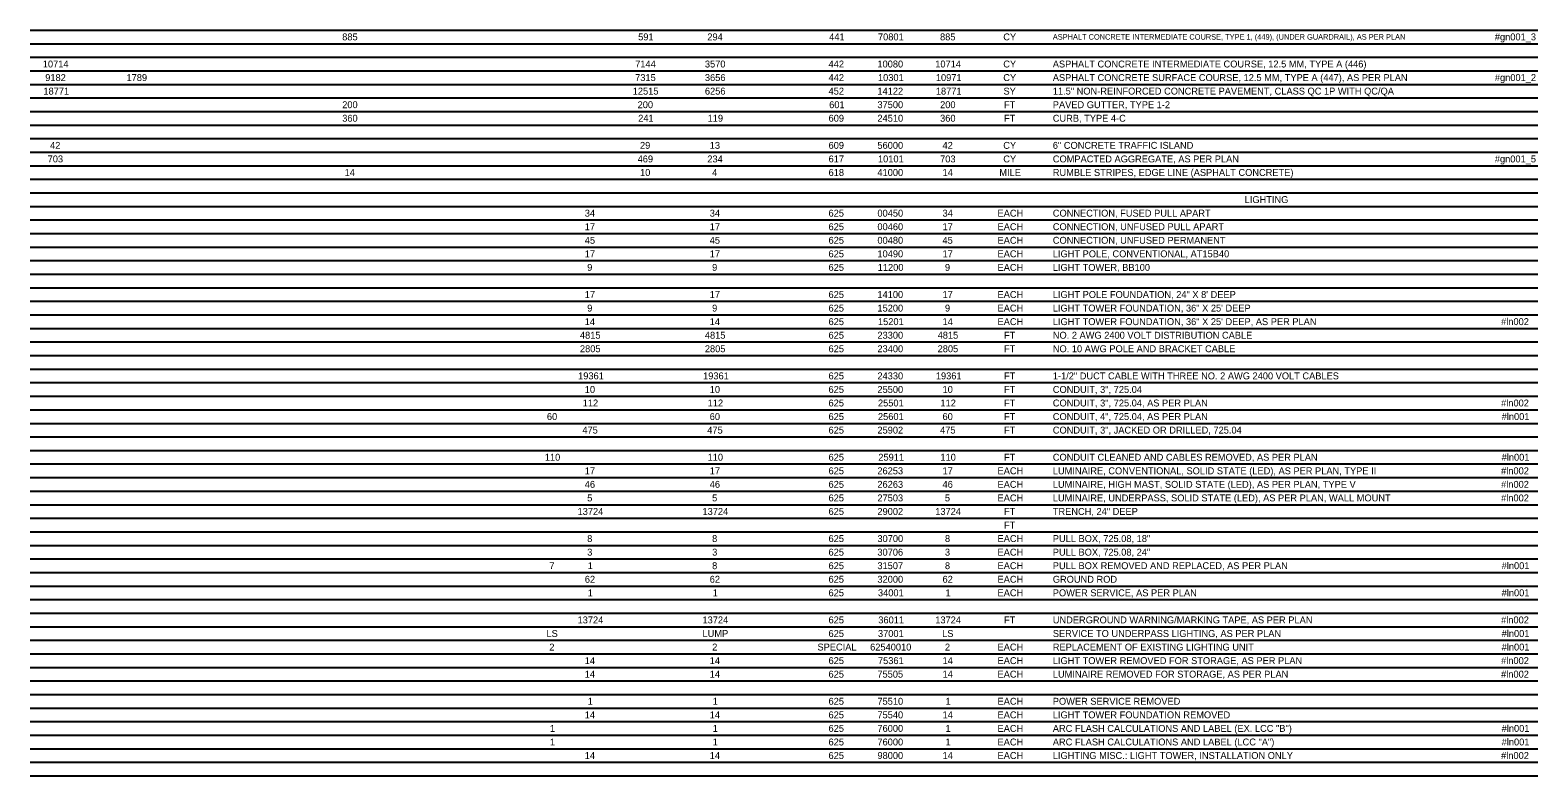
# Model space of a CAD drawing. Extents: x -542 to 295, y -281 to 32.
# Drawn here: x -366.31 to -335.81, y -89.91 to -74.81 of the extents above; entities that cross this region are included whole.
import ezdxf

# ---------------------------------------------------------------- set-up
doc = ezdxf.new("R2010")
doc.units = 0
doc.layers.add('SH_Data', color=7, linetype='Continuous')
doc.layers.add('SH_Text', color=7, linetype='Continuous')

msp = doc.modelspace()

# ---------------------------------------------------------------- linework, layer by layer
at = {"layer": 'SH_Data'}
for p, q in [((-366.307, -74.812), (-335.807, -74.812)), ((-366.307, -75.087), (-335.807, -75.087)), ((-366.307, -75.361), (-335.807, -75.361)), ((-366.307, -75.636), (-335.807, -75.636)), ((-366.307, -75.91), (-335.807, -75.91)), ((-366.307, -76.185), (-335.807, -76.185)), ((-366.307, -76.459), (-335.807, -76.459)), ((-366.307, -76.734), (-335.807, -76.734)), ((-366.307, -77.008), (-335.807, -77.008)), ((-366.307, -77.283), (-335.807, -77.283)), ((-366.307, -77.557), (-335.807, -77.557)), ((-366.307, -77.832), (-335.807, -77.832)), ((-366.307, -78.106), (-335.807, -78.106)), ((-366.307, -78.381), (-335.807, -78.381)), ((-366.307, -78.655), (-335.807, -78.655)), ((-366.307, -78.93), (-335.807, -78.93)), ((-366.307, -79.204), (-335.807, -79.204)), ((-366.307, -79.479), (-335.807, -79.479)), ((-366.307, -79.753), (-335.807, -79.753)), ((-366.307, -80.028), (-335.807, -80.028)), ((-366.307, -80.302), (-335.807, -80.302)), ((-366.307, -80.577), (-335.807, -80.577)), ((-366.307, -80.851), (-335.807, -80.851)), ((-366.307, -81.126), (-335.807, -81.126)), ((-366.307, -81.4), (-335.807, -81.4)), ((-366.307, -81.675), (-335.807, -81.675)), ((-366.307, -81.949), (-335.807, -81.949)), ((-366.307, -82.224), (-335.807, -82.224)), ((-366.307, -82.498), (-335.807, -82.498)), ((-366.307, -82.773), (-335.807, -82.773)), ((-366.307, -83.047), (-335.807, -83.047)), ((-366.307, -83.322), (-335.807, -83.322)), ((-366.307, -83.596), (-335.807, -83.596)), ((-366.307, -83.871), (-335.807, -83.871)), ((-366.307, -84.145), (-335.807, -84.145)), ((-366.307, -84.42), (-335.807, -84.42)), ((-366.307, -84.694), (-335.807, -84.694)), ((-366.307, -84.969), (-335.807, -84.969)), ((-366.307, -85.243), (-335.807, -85.243)), ((-366.307, -85.518), (-335.807, -85.518)), ((-366.307, -85.792), (-335.807, -85.792)), ((-366.307, -86.067), (-335.807, -86.067)), ((-366.307, -86.341), (-335.807, -86.341)), ((-366.307, -86.616), (-335.807, -86.616)), ((-366.307, -86.89), (-335.807, -86.89)), ((-366.307, -87.165), (-335.807, -87.165)), ((-366.307, -87.44), (-335.807, -87.44)), ((-366.307, -87.714), (-335.807, -87.714)), ((-366.307, -87.989), (-335.807, -87.989)), ((-366.307, -88.263), (-335.807, -88.263)), ((-366.307, -88.538), (-335.807, -88.538)), ((-366.307, -88.812), (-335.807, -88.812)), ((-366.307, -89.087), (-335.807, -89.087)), ((-366.307, -89.361), (-335.807, -89.361)), ((-366.307, -89.636), (-335.807, -89.636)), ((-366.307, -89.91), (-335.807, -89.91))]:
    msp.add_line(p, q, dxfattribs=at)

# ---------------------------------------------------------------- texts
at = {"layer": 'SH_Text'}
for s, height, p in [('885', 0.14, (-359.994, -75.019)), ('591', 0.14, (-354.007, -75.019)), ('294', 0.14, (-352.608, -75.019)), ('441', 0.14, (-350.143, -75.019)), ('70801', 0.14, (-349.156, -75.019)), ('885', 0.14, (-347.9, -75.019)), ('CY', 0.14, (-346.621, -75.019)), ('ASPHALT CONCRETE INTERMEDIATE COURSE, TYPE 1, (449), (UNDER GUARDRAIL), AS PER PLAN', 0.112, (-345.619, -75.005)), ('#gn001_3', 0.14, (-336.677, -75.019)), ('10714', 0.14, (-366.051, -75.568)), ('7144', 0.14, (-354.067, -75.568)), ('3570', 0.14, (-352.657, -75.568)), ('442', 0.14, (-350.155, -75.568)), ('10080', 0.14, (-349.167, -75.568)), ('10714', 0.14, (-347.997, -75.568)), ('CY', 0.14, (-346.621, -75.568)), ('ASPHALT CONCRETE INTERMEDIATE COURSE, 12.5 MM, TYPE A (446)', 0.14, (-345.619, -75.568)), ('9182', 0.14, (-366.002, -75.843)), ('1789', 0.14, (-364.358, -75.843)), ('7315', 0.14, (-354.068, -75.843)), ('3656', 0.14, (-352.657, -75.843)), ('442', 0.14, (-350.155, -75.843)), ('10301', 0.14, (-349.156, -75.843)), ('10971', 0.14, (-347.985, -75.843)), ('CY', 0.14, (-346.621, -75.843)), ('ASPHALT CONCRETE SURFACE COURSE, 12.5 MM, TYPE A (447), AS PER PLAN', 0.14, (-345.619, -75.843)), ('#gn001_2', 0.14, (-336.676, -75.843)), ('18771', 0.14, (-366.039, -76.117)), ('200', 0.14, (-359.994, -76.392)), ('12515', 0.14, (-354.117, -76.117)), ('200', 0.14, (-354.018, -76.392)), ('6256', 0.14, (-352.657, -76.117)), ('452', 0.14, (-350.155, -76.117)), ('601', 0.14, (-350.143, -76.392)), ('37500', 0.14, (-349.167, -76.392)), ('14122', 0.14, (-349.167, -76.117)), ('18771', 0.14, (-347.985, -76.117)), ('200', 0.14, (-347.899, -76.392)), ('SY', 0.14, (-346.617, -76.117)), ('11.5" NON-REINFORCED CONCRETE PAVEMENT, CLASS QC 1P WITH QC/QA', 0.14, (-345.619, -76.117)), ('PAVED GUTTER, TYPE 1-2', 0.14, (-345.619, -76.392)), ('360', 0.14, (-359.994, -76.666)), ('241', 0.14, (-354.007, -76.666)), ('119', 0.14, (-352.602, -76.666)), ('609', 0.14, (-350.155, -76.666)), ('24510', 0.14, (-349.167, -76.666)), ('360', 0.14, (-347.899, -76.666)), ('FT', 0.14, (-346.606, -76.392)), ('FT', 0.14, (-346.606, -76.666)), ('CURB, TYPE 4-C', 0.14, (-345.619, -76.666)), ('42', 0.14, (-365.904, -77.215)), ('29', 0.14, (-353.97, -77.215)), ('13', 0.14, (-352.559, -77.215)), ('609', 0.14, (-350.155, -77.215)), ('56000', 0.14, (-349.167, -77.215)), ('42', 0.14, (-347.85, -77.215)), ('CY', 0.14, (-346.621, -77.215)), ('6" CONCRETE TRAFFIC ISLAND', 0.14, (-345.619, -77.215)), ('703', 0.14, (-365.953, -77.49)), ('469', 0.14, (-354.018, -77.49)), ('234', 0.14, (-352.608, -77.49)), ('617', 0.14, (-350.155, -77.49)), ('10101', 0.14, (-349.156, -77.49)), ('703', 0.14, (-347.899, -77.49)), ('CY', 0.14, (-346.621, -77.49)), ('COMPACTED AGGREGATE, AS PER PLAN', 0.14, (-345.619, -77.49)), ('#gn001_5', 0.14, (-336.677, -77.49)), ('14', 0.14, (-359.945, -77.764)), ('10', 0.14, (-353.969, -77.764)), ('4', 0.14, (-352.51, -77.764)), ('618', 0.14, (-350.155, -77.764)), ('41000', 0.14, (-349.167, -77.764)), ('14', 0.14, (-347.85, -77.764)), ('MILE', 0.14, (-346.701, -77.764)), ('RUMBLE STRIPES, EDGE LINE (ASPHALT CONCRETE)', 0.14, (-345.619, -77.764)), ('LIGHTING', 0.14, (-341.738, -78.313)), ('34', 0.14, (-355.087, -78.588)), ('34', 0.14, (-352.559, -78.588)), ('625', 0.14, (-350.156, -78.588)), ('00450', 0.14, (-349.167, -78.588)), ('34', 0.14, (-347.85, -78.588)), ('EACH', 0.14, (-346.737, -78.588)), ('CONNECTION, FUSED PULL APART', 0.14, (-345.619, -78.588)), ('17', 0.14, (-355.087, -78.862)), ('17', 0.14, (-352.559, -78.862)), ('625', 0.14, (-350.156, -78.862)), ('625', 0.14, (-350.156, -79.137)), ('00460', 0.14, (-349.167, -78.862)), ('00480', 0.14, (-349.167, -79.137)), ('17', 0.14, (-347.85, -78.862)), ('EACH', 0.14, (-346.737, -78.862)), ('EACH', 0.14, (-346.737, -79.137)), ('CONNECTION, UNFUSED PULL APART', 0.14, (-345.619, -78.862)), ('CONNECTION, UNFUSED PERMANENT', 0.14, (-345.619, -79.137)), ('45', 0.14, (-355.087, -79.137)), ('17', 0.14, (-355.087, -79.411)), ('45', 0.14, (-352.56, -79.137)), ('17', 0.14, (-352.559, -79.411)), ('625', 0.14, (-350.156, -79.411)), ('10490', 0.14, (-349.167, -79.411)), ('45', 0.14, (-347.851, -79.137)), ('17', 0.14, (-347.85, -79.411)), ('EACH', 0.14, (-346.737, -79.411)), ('LIGHT POLE, CONVENTIONAL, AT15B40', 0.14, (-345.619, -79.411)), ('9', 0.14, (-355.038, -79.686)), ('9', 0.14, (-352.511, -79.686)), ('625', 0.14, (-350.156, -79.686)), ('11200', 0.14, (-349.161, -79.686)), ('9', 0.14, (-347.801, -79.686)), ('EACH', 0.14, (-346.737, -79.686)), ('LIGHT TOWER, BB100', 0.14, (-345.619, -79.686)), ('17', 0.14, (-355.087, -80.235)), ('17', 0.14, (-352.559, -80.235)), ('625', 0.14, (-350.156, -80.235)), ('14100', 0.14, (-349.167, -80.235)), ('17', 0.14, (-347.85, -80.235)), ('EACH', 0.14, (-346.737, -80.235)), ('LIGHT POLE FOUNDATION, 24" X 8\' DEEP', 0.14, (-345.619, -80.235)), ('9', 0.14, (-355.038, -80.51)), ('9', 0.14, (-352.511, -80.51)), ('625', 0.14, (-350.156, -80.51)), ('15200', 0.14, (-349.167, -80.51)), ('9', 0.14, (-347.801, -80.51)), ('EACH', 0.14, (-346.737, -80.51)), ('LIGHT TOWER FOUNDATION, 36" X 25\' DEEP', 0.14, (-345.619, -80.51)), ('14', 0.14, (-355.087, -80.784)), ('14', 0.14, (-352.559, -80.784)), ('625', 0.14, (-350.156, -80.784)), ('15201', 0.14, (-349.156, -80.784)), ('14', 0.14, (-347.85, -80.784)), ('EACH', 0.14, (-346.737, -80.784)), ('LIGHT TOWER FOUNDATION, 36" X 25\' DEEP, AS PER PLAN', 0.14, (-345.619, -80.784)), ('#ln002', 0.14, (-336.55, -80.784)), ('4815', 0.14, (-355.185, -81.059)), ('4815', 0.14, (-352.658, -81.059)), ('625', 0.14, (-350.156, -81.059)), ('23300', 0.14, (-349.167, -81.059)), ('4815', 0.14, (-347.949, -81.059)), ('FT', 0.14, (-346.606, -81.059)), ('NO. 2 AWG 2400 VOLT DISTRIBUTION CABLE', 0.14, (-345.619, -81.059)), ('2805', 0.14, (-355.185, -81.333)), ('2805', 0.14, (-352.658, -81.333)), ('625', 0.14, (-350.156, -81.333)), ('23400', 0.14, (-349.167, -81.333)), ('2805', 0.14, (-347.949, -81.333)), ('FT', 0.14, (-346.606, -81.333)), ('NO. 10 AWG POLE AND BRACKET CABLE', 0.14, (-345.619, -81.333)), ('19361', 0.14, (-355.222, -81.882)), ('19361', 0.14, (-352.694, -81.882)), ('625', 0.14, (-350.156, -81.882)), ('24330', 0.14, (-349.167, -81.882)), ('19361', 0.14, (-347.985, -81.882)), ('1-1/2" DUCT CABLE WITH THREE NO. 2 AWG 2400 VOLT CABLES', 0.14, (-345.619, -81.882)), ('10', 0.14, (-355.087, -82.157)), ('10', 0.14, (-352.559, -82.157)), ('625', 0.14, (-350.156, -82.157)), ('25500', 0.14, (-349.167, -82.157)), ('10', 0.14, (-347.85, -82.157)), ('FT', 0.14, (-346.606, -81.882)), ('FT', 0.14, (-346.606, -82.157)), ('CONDUIT, 3", 725.04', 0.14, (-345.619, -82.157)), ('112', 0.14, (-355.129, -82.431)), ('112', 0.14, (-352.601, -82.431)), ('625', 0.14, (-350.156, -82.431)), ('25501', 0.14, (-349.156, -82.431)), ('112', 0.14, (-347.892, -82.431)), ('FT', 0.14, (-346.606, -82.431)), ('CONDUIT, 3", 725.04, AS PER PLAN', 0.14, (-345.619, -82.431)), ('#ln002', 0.14, (-336.55, -82.431)), ('60', 0.14, (-355.853, -82.706)), ('60', 0.14, (-352.559, -82.706)), ('625', 0.14, (-350.156, -82.706)), ('25601', 0.14, (-349.156, -82.706)), ('60', 0.14, (-347.85, -82.706)), ('FT', 0.14, (-346.606, -82.706)), ('CONDUIT, 4", 725.04, AS PER PLAN', 0.14, (-345.619, -82.706)), ('#ln001', 0.14, (-336.539, -82.706)), ('475', 0.14, (-355.136, -82.98)), ('475', 0.14, (-352.609, -82.98)), ('625', 0.14, (-350.156, -82.98)), ('25902', 0.14, (-349.167, -82.98)), ('475', 0.14, (-347.9, -82.98)), ('FT', 0.14, (-346.606, -82.98)), ('CONDUIT, 3", JACKED OR DRILLED, 725.04', 0.14, (-345.619, -82.98)), ('110', 0.14, (-355.895, -83.529)), ('110', 0.14, (-352.602, -83.529)), ('625', 0.14, (-350.156, -83.529)), ('25911', 0.14, (-349.149, -83.529)), ('110', 0.14, (-347.893, -83.529)), ('FT', 0.14, (-346.606, -83.529)), ('CONDUIT CLEANED AND CABLES REMOVED, AS PER PLAN', 0.14, (-345.619, -83.529)), ('#ln001', 0.14, (-336.539, -83.529)), ('17', 0.14, (-355.087, -83.804)), ('17', 0.14, (-352.559, -83.804)), ('625', 0.14, (-350.156, -83.804)), ('26253', 0.14, (-349.168, -83.804)), ('17', 0.14, (-347.85, -83.804)), ('EACH', 0.14, (-346.737, -83.804)), ('LUMINAIRE, CONVENTIONAL, SOLID STATE (LED), AS PER PLAN, TYPE II', 0.14, (-345.619, -83.804)), ('#ln002', 0.14, (-336.55, -83.804)), ('46', 0.14, (-355.087, -84.078)), ('46', 0.14, (-352.559, -84.078)), ('625', 0.14, (-350.156, -84.078)), ('26263', 0.14, (-349.168, -84.078)), ('46', 0.14, (-347.85, -84.078)), ('EACH', 0.14, (-346.737, -84.078)), ('LUMINAIRE, HIGH MAST, SOLID STATE (LED), AS PER PLAN, TYPE V', 0.14, (-345.619, -84.078)), ('#ln002', 0.14, (-336.55, -84.078)), ('5', 0.14, (-355.038, -84.353)), ('5', 0.14, (-352.511, -84.353)), ('625', 0.14, (-350.156, -84.353)), ('27503', 0.14, (-349.168, -84.353)), ('5', 0.14, (-347.802, -84.353)), ('EACH', 0.14, (-346.737, -84.353)), ('LUMINAIRE, UNDERPASS, SOLID STATE (LED), AS PER PLAN, WALL MOUNT', 0.14, (-345.619, -84.353)), ('#ln002', 0.14, (-336.55, -84.353)), ('13724', 0.14, (-355.233, -84.627)), ('13724', 0.14, (-352.706, -84.627)), ('625', 0.14, (-350.156, -84.627)), ('29002', 0.14, (-349.167, -84.627)), ('13724', 0.14, (-347.997, -84.627)), ('FT', 0.14, (-346.606, -84.627)), ('FT', 0.14, (-346.606, -84.902)), ('TRENCH, 24" DEEP', 0.14, (-345.619, -84.627)), ('8', 0.14, (-355.038, -85.176)), ('8', 0.14, (-352.511, -85.176)), ('625', 0.14, (-350.156, -85.176)), ('30700', 0.14, (-349.167, -85.176)), ('8', 0.14, (-347.801, -85.176)), ('EACH', 0.14, (-346.737, -85.176)), ('PULL BOX, 725.08, 18"', 0.14, (-345.619, -85.176)), ('3', 0.14, (-355.038, -85.451)), ('3', 0.14, (-352.51, -85.451)), ('625', 0.14, (-350.156, -85.451)), ('30706', 0.14, (-349.168, -85.451)), ('3', 0.14, (-347.801, -85.451)), ('EACH', 0.14, (-346.737, -85.451)), ('PULL BOX, 725.08, 24"', 0.14, (-345.619, -85.451)), ('7', 0.14, (-355.804, -85.725)), ('1', 0.14, (-355.026, -85.725)), ('8', 0.14, (-352.511, -85.725)), ('625', 0.14, (-350.156, -85.725)), ('31507', 0.14, (-349.168, -85.725)), ('8', 0.14, (-347.801, -85.725)), ('EACH', 0.14, (-346.737, -85.725)), ('PULL BOX REMOVED AND REPLACED, AS PER PLAN', 0.14, (-345.619, -85.725)), ('#ln001', 0.14, (-336.539, -85.725)), ('62', 0.14, (-355.086, -86)), ('62', 0.14, (-352.559, -86)), ('625', 0.14, (-350.156, -86)), ('32000', 0.14, (-349.167, -86)), ('62', 0.14, (-347.85, -86)), ('EACH', 0.14, (-346.737, -86)), ('GROUND ROD', 0.14, (-345.619, -86)), ('1', 0.14, (-355.026, -86.274)), ('1', 0.14, (-352.499, -86.274)), ('625', 0.14, (-350.156, -86.274)), ('34001', 0.14, (-349.156, -86.274)), ('1', 0.14, (-347.79, -86.274)), ('EACH', 0.14, (-346.737, -86.274)), ('POWER SERVICE, AS PER PLAN', 0.14, (-345.619, -86.274)), ('#ln001', 0.14, (-336.539, -86.274)), ('13724', 0.14, (-355.233, -86.823)), ('13724', 0.14, (-352.706, -86.823)), ('625', 0.14, (-350.156, -86.823)), ('36011', 0.14, (-349.149, -86.823)), ('13724', 0.14, (-347.997, -86.823)), ('FT', 0.14, (-346.606, -86.823)), ('UNDERGROUND WARNING/MARKING TAPE, AS PER PLAN', 0.14, (-345.619, -86.823)), ('#ln002', 0.14, (-336.55, -86.823)), ('LS', 0.14, (-355.862, -87.098)), ('LUMP', 0.14, (-352.705, -87.098)), ('625', 0.14, (-350.156, -87.098)), ('37001', 0.14, (-349.156, -87.098)), ('LS', 0.14, (-347.859, -87.098)), ('SERVICE TO UNDERPASS LIGHTING, AS PER PLAN', 0.14, (-345.619, -87.098)), ('#ln001', 0.14, (-336.539, -87.098)), ('#ln001', 0.14, (-336.539, -87.372)), ('2', 0.14, (-355.804, -87.372)), ('14', 0.14, (-355.087, -87.647)), ('14', 0.14, (-352.559, -87.647)), ('2', 0.14, (-352.51, -87.372)), ('SPECIAL', 0.14, (-350.38, -87.372)), ('625', 0.14, (-350.156, -87.647)), ('62540010', 0.14, (-349.314, -87.372)), ('75361', 0.14, (-349.156, -87.647)), ('14', 0.14, (-347.85, -87.647)), ('2', 0.14, (-347.801, -87.372)), ('EACH', 0.14, (-346.737, -87.372)), ('EACH', 0.14, (-346.737, -87.647)), ('REPLACEMENT OF EXISTING LIGHTING UNIT', 0.14, (-345.619, -87.372)), ('LIGHT TOWER REMOVED FOR STORAGE, AS PER PLAN', 0.14, (-345.619, -87.647)), ('#ln002', 0.14, (-336.55, -87.647)), ('14', 0.14, (-355.087, -87.921)), ('14', 0.14, (-352.559, -87.921)), ('625', 0.14, (-350.156, -87.921)), ('75505', 0.14, (-349.168, -87.921)), ('14', 0.14, (-347.85, -87.921)), ('EACH', 0.14, (-346.737, -87.921)), ('LUMINAIRE REMOVED FOR STORAGE, AS PER PLAN', 0.14, (-345.619, -87.921)), ('#ln002', 0.14, (-336.55, -87.921)), ('1', 0.14, (-355.026, -88.47)), ('1', 0.14, (-352.499, -88.47)), ('625', 0.14, (-350.156, -88.47)), ('75510', 0.14, (-349.167, -88.47)), ('1', 0.14, (-347.79, -88.47)), ('EACH', 0.14, (-346.737, -88.47)), ('POWER SERVICE REMOVED', 0.14, (-345.619, -88.47)), ('14', 0.14, (-355.087, -88.745)), ('14', 0.14, (-352.559, -88.745)), ('625', 0.14, (-350.156, -88.745)), ('75540', 0.14, (-349.167, -88.745)), ('14', 0.14, (-347.85, -88.745)), ('EACH', 0.14, (-346.737, -88.745)), ('LIGHT TOWER FOUNDATION REMOVED', 0.14, (-345.619, -88.745)), ('1', 0.14, (-355.792, -89.019)), ('1', 0.14, (-352.499, -89.019)), ('625', 0.14, (-350.156, -89.019)), ('76000', 0.14, (-349.167, -89.019)), ('1', 0.14, (-347.79, -89.019)), ('EACH', 0.14, (-346.737, -89.019)), ('ARC FLASH CALCULATIONS AND LABEL (EX. LCC "B")', 0.14, (-345.619, -89.019)), ('#ln001', 0.14, (-336.539, -89.019)), ('1', 0.14, (-355.792, -89.294)), ('1', 0.14, (-352.499, -89.294)), ('625', 0.14, (-350.156, -89.294)), ('76000', 0.14, (-349.167, -89.294)), ('1', 0.14, (-347.79, -89.294)), ('EACH', 0.14, (-346.737, -89.294)), ('ARC FLASH CALCULATIONS AND LABEL (LCC "A")', 0.14, (-345.619, -89.294)), ('#ln001', 0.14, (-336.539, -89.294)), ('14', 0.14, (-355.087, -89.568)), ('14', 0.14, (-352.559, -89.568)), ('625', 0.14, (-350.156, -89.568)), ('98000', 0.14, (-349.167, -89.568)), ('14', 0.14, (-347.85, -89.568)), ('EACH', 0.14, (-346.737, -89.568)), ('LIGHTING MISC.: LIGHT TOWER, INSTALLATION ONLY', 0.14, (-345.619, -89.568)), ('#ln002', 0.14, (-336.55, -89.568))]:
    msp.add_text(s, height=height, dxfattribs=at).set_placement(p)

doc.saveas('drawing.dxf')
